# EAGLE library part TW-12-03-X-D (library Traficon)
SAMTEC TW-10-03-X-D
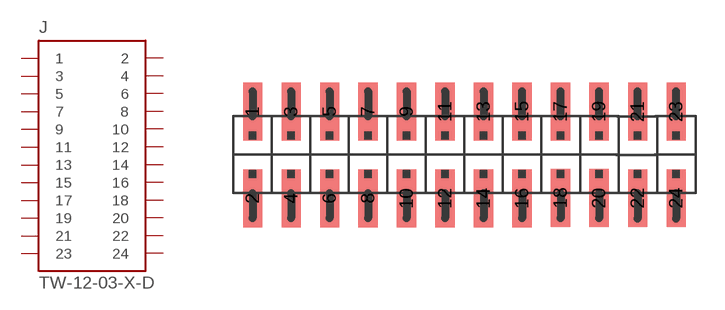
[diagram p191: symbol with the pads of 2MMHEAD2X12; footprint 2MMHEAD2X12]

Designator prefix J

## TW-12-03-X-D  [2MMHEAD2X12]
1  1  pas
2  2  pas
3  3  pas
4  4  pas
5  5  pas
6  6  pas
7  7  pas
8  8  pas
9  9  pas
10  10  pas
11  11  pas
12  12  pas
13  13  pas
14  14  pas
15  15  pas
16  16  pas
17  17
18  18
19  19
20  20
21  21
22  22
23  23
24  24

## Footprint 2MMHEAD2X12 (pad centres in mm)
smd 1 x 3: 1 -10.962,2.295; 2 -10.962,-2.225; 3 -8.962,2.295; 4 -8.962,-2.225; 5 -6.962,2.295; 6 -6.962,-2.225; 7 -4.962,2.295; 8 -4.962,-2.225; 9 -2.962,2.295; 10 -2.962,-2.225; 11 -0.962,2.295; 12 -0.962,-2.225; 13 1.038,2.295; 14 1.038,-2.225; 15 3.038,2.295; 16 3.038,-2.225; 17 5.038,2.295; 18 5.038,-2.205; 19 7.038,2.295; 20 7.038,-2.205; 21 9.044,2.293; 22 9.044,-2.207; 23 11.044,2.293; 24 11.044,-2.207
